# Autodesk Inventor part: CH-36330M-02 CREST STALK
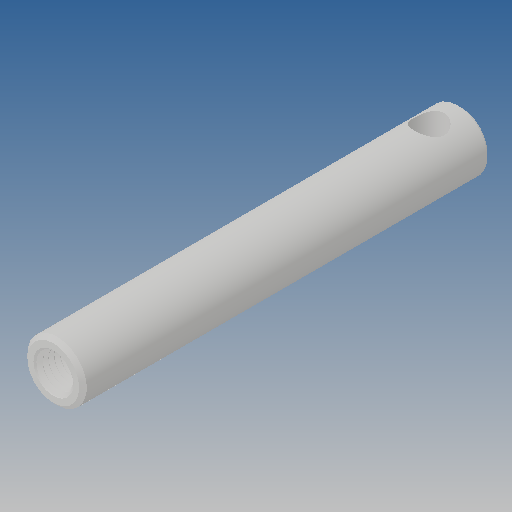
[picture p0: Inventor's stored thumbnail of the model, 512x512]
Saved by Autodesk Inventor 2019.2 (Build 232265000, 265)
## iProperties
Created: 2012-09
Part Number: CH-36330M-02 CREST STALK
Material: Ogólny
Document SubType Name: Modeling
Designer: CADENGINEERING4
Density: 1 g/cm^3
Appearance: Domyślna
Author: CADENGINEERING4
Revision Number: ÈÎºÎ
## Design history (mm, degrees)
feature "ÇÐ³ý-É¨Ãè1"
node "Bryła1"
